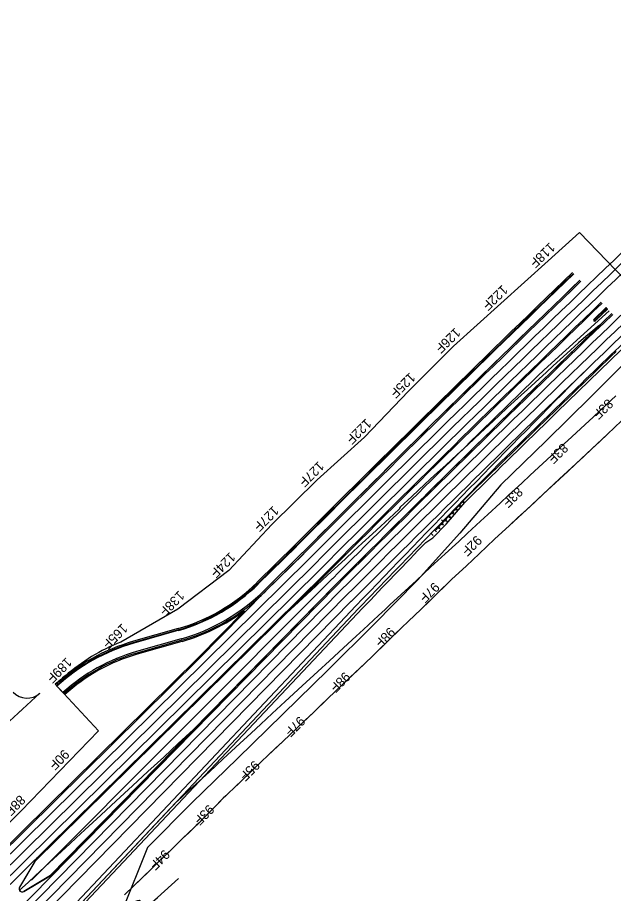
# Model space of a CAD drawing. Extents: x 2163396 to 2173129, y 605545 to 614595.
# Drawn here: x 2164110 to 2165051, y 606275 to 607658 of the extents above; entities that cross this region are included whole.
import ezdxf

# ---------------------------------------------------------------- set-up
doc = ezdxf.new("R2010")
doc.units = 0
for name, color, linetype in [('RD_PD_AsphRem', 7, 'Continuous'), ('RD_PD_CstnLmt', 7, 'Continuous'), ('RD_PD_DR_Ditch', 7, 'Continuous'), ('RD_PD_EarthShd', 7, 'Continuous'), ('RD_PD_Final_LnLine', 7, 'Continuous'), ('RD_PD_Final_TrvlWay', 7, 'Continuous'), ('RD_PD_GR', 7, 'Continuous'), ('RD_PD_MedBWall', 7, 'Continuous'), ('RD_PD_MedGR', 7, 'Continuous'), ('RD_PD_TX_CstnLmt', 7, 'Continuous')]:
    doc.layers.add(name, color=color, linetype=linetype)

msp = doc.modelspace()

# ---------------------------------------------------------------- linework, layer by layer
at = {"layer": 'RD_PD_AsphRem'}
for p, q in [((2164161.6, 606303.2), (2164392.3, 606538.4)), ((2164363.7, 606512.1), (2164387.6, 606534.1)), ((2164387.6, 606534.1), (2164392.3, 606538.4)), ((2164359.8, 606418.6), (2164041.5, 606080.9)), ((2164202.4, 606362.7), (2164216.2, 606375.5)), ((2164137.3, 606325.6), (2164113, 606285)), ((2164112.9, 606280.1), (2164126.6, 606292.6)), ((2164119.9, 606278.2), (2164161.6, 606303.2))]:
    msp.add_line(p, q, dxfattribs=at)
for points in [[(2165028.9, 607172.3), (2165025.7, 607169.6), (2165018.2, 607163.2), (2165007.3, 607154.1), (2164995.5, 607144.2), (2164977.1, 607127.7), (2164966.3, 607117.9), (2164955.5, 607107.9), (2164944.9, 607098.2), (2164927.2, 607081.9), (2164914.8, 607070.7), (2164904.8, 607061.6), (2164883.6, 607042.3), (2164870.3, 607029.7), (2164861.4, 607021.4), (2164840.2, 607001.5), (2164821.2, 606984.1), (2164803.3, 606967.5), (2164786.1, 606951.4), (2164768.4, 606935.6), (2164752.9, 606921.1), (2164732.2, 606901.8), (2164714.1, 606884.8), (2164713, 606883.4), (2164712.9, 606882.7), (2164712.9, 606882.2), (2164703.9, 606874), (2164683.3, 606855.1), (2164670.3, 606843.1), (2164654.1, 606828.2), (2164640.5, 606815.5), (2164627.4, 606803.2), (2164621.4, 606797.6), (2164599.2, 606777.4), (2164573.5, 606753.4), (2164547.1, 606729.2), (2164535.6, 606718.5)], [(2165054.3, 607060.5), (2165039.8, 607047), (2165018.4, 607027.2), (2165006.1, 607015.5), (2164984.9, 606995.8), (2164973.1, 606984.8), (2164952.5, 606966), (2164939.3, 606953.9), (2164919.3, 606935.2), (2164905.8, 606922.8), (2164885.2, 606903.8), (2164871.6, 606891.2), (2164852.1, 606873.2), (2164840.7, 606862.7), (2164820, 606843.7), (2164806.4, 606830.9), (2164785.2, 606811.5), (2164762, 606790.1), (2164739.6, 606769.4), (2164715.3, 606747), (2164697.8, 606730.7), (2164690.1, 606723.5), (2164679.7, 606713.8), (2164655.8, 606691.9), (2164644.6, 606681.5), (2164624.6, 606663), (2164602.6, 606642.6), (2164584.1, 606625.6), (2164559.3, 606602.8), (2164532.5, 606578), (2164512.1, 606559.2), (2164494.1, 606542.5), (2164478.6, 606528.2), (2164461, 606512), (2164434.7, 606487.6), (2164412.7, 606467.3), (2164401.8, 606457.1), (2164391.6, 606447.8), (2164382.5, 606439.6), (2164368.7, 606426.7), (2164359.8, 606418.6)], [(2164278.7, 606273), (2164293.4, 606287.2), (2164303.3, 606296.8), (2164318.1, 606311.1), (2164328, 606320.6), (2164343.6, 606335.5), (2164355.9, 606347.5), (2164371, 606362.2), (2164388.2, 606378.8), (2164395.9, 606386.3), (2164408.3, 606398.9), (2164419.3, 606409.8), (2164434.7, 606425.3), (2164442.9, 606433.4), (2164451.8, 606441.8), (2164465.3, 606454.8), (2164483.7, 606472.2), (2164505.8, 606493.4), (2164528.8, 606515.2), (2164551.3, 606536.4), (2164576.9, 606560.9), (2164599.5, 606582.7), (2164622.2, 606604.4), (2164646.9, 606627.5), (2164670.3, 606649.8), (2164693.5, 606672.3), (2164716.8, 606695), (2164726.8, 606704.7), (2164747.2, 606724), (2164772.9, 606749.2), (2164794.8, 606770.6), (2164818.4, 606792.5), (2164838.6, 606811.5), (2164862.8, 606834.5), (2164886.5, 606856.1), (2164913.3, 606880.8), (2164939.7, 606905.2), (2164965.6, 606929.4), (2164991.3, 606953.3), (2165016.6, 606977), (2165041.4, 607000.4), (2165063.3, 607021.2)], [(2164392.3, 606538.4), (2164392.3, 606538.4), (2164614.2, 606764.6)], [(2164535.6, 606718.5), (2164137.3, 606325.6), (2164137.3, 606325.6)], [(2164392.3, 606538.4), (2164387.6, 606534.1), (2164363.7, 606512.1), (2164340.6, 606490.5), (2164315.6, 606467.5), (2164291.2, 606444.9), (2164265.5, 606421.1), (2164241.3, 606398.7), (2164216.2, 606375.5), (2164202.4, 606362.7), (2164192.2, 606353.3), (2164173, 606335.6), (2164160.4, 606323.9), (2164137.7, 606302.8), (2164126.6, 606292.6), (2164112.9, 606280.1)], [(2164315.6, 606467.5), (2164340.6, 606490.5), (2164363.7, 606512.1)], [(2164265.5, 606421.1), (2164291.2, 606444.9), (2164315.6, 606467.5)], [(2164216.2, 606375.5), (2164241.3, 606398.7), (2164265.5, 606421.1)], [(2164126.6, 606292.6), (2164137.7, 606302.8), (2164160.4, 606323.9), (2164173, 606335.6), (2164192.2, 606353.3), (2164202.4, 606362.7)]]:
    msp.add_lwpolyline(points, dxfattribs=at)
for centre, radius, start, end in [((2185842.9, 585582.7), 29988.8, 133.95223, 135.0633), ((2164117.3, 606282.5), 5, 149.0992, 208.9048), ((2164117.3, 606282.5), 5, 208.9048, 301.0267)]:
    msp.add_arc(centre, radius, start, end, dxfattribs=at)
at = {"layer": 'RD_PD_CstnLmt'}
for p, q in [((2164947.6, 607273.6), (2164997, 607318.7)), ((2165134.6, 607175.3), (2164997, 607318.7)), ((2164947.6, 607273.6), (2164872.8, 607206.5)), ((2164872.8, 607206.5), (2164798.3, 607139.1)), ((2164798.3, 607139.1), (2164727.1, 607068.3)), ((2165085.8, 607130.2), (2165015.3, 607059.6)), ((2164727.1, 607068.3), (2164657.8, 606995.6)), ((2165015.3, 607059.6), (2164944.3, 606989.6)), ((2164657.8, 606995.6), (2164583.1, 606928.3)), ((2164944.3, 606989.6), (2164872.7, 606920.2)), ((2164583.1, 606928.3), (2164511.6, 606857.8)), ((2164872.7, 606920.2), (2164808.1, 606843.7)), ((2164511.6, 606857.8), (2164443.2, 606784.7)), ((2164808.1, 606843.7), (2164741.1, 606769.6)), ((2164443.2, 606784.7), (2164362.7, 606723.8)), ((2164741.1, 606769.6), (2164671.1, 606698.7)), ((2164362.7, 606723.8), (2164273, 606672)), ((2164671.1, 606698.7), (2164600.1, 606628.2)), ((2164600.1, 606628.2), (2164528.8, 606558.2)), ((2164237.7, 606532), (2164169.5, 606605.3)), ((2164528.8, 606558.2), (2164457.3, 606488.3)), ((2164237.7, 606532), (2164115.4, 606405.5)), ((2164457.3, 606488.3), (2164385.4, 606418.7)), ((2164385.4, 606418.7), (2164315.1, 606347.6)), ((2164115.4, 606405.5), (2164043.9, 606335.6)), ((2164315.1, 606347.6), (2164274.5, 606246.8))]:
    msp.add_line(p, q, dxfattribs=at)
msp.add_lwpolyline([(2165052.4, 607010.8), (2165041.4, 607000.4), (2165029, 606988.7), (2165016.6, 606977), (2165003.9, 606965.1), (2164991.3, 606953.3), (2164978.4, 606941.3), (2164952.7, 606917.3), (2164939.7, 606905.2), (2164926.5, 606893), (2164913.3, 606880.8), (2164899.9, 606868.4), (2164886.5, 606856.1), (2164874.7, 606845.3), (2164862.8, 606834.5), (2164850.7, 606823), (2164838.6, 606811.5), (2164828.5, 606802), (2164818.4, 606792.5), (2164806.6, 606781.5), (2164794.8, 606770.6), (2164783.9, 606759.9), (2164772.9, 606749.2), (2164760, 606736.6), (2164747.2, 606724), (2164726.8, 606704.7), (2164716.8, 606695), (2164705.2, 606683.7), (2164693.5, 606672.3), (2164681.9, 606661.1), (2164670.3, 606649.8), (2164658.6, 606638.7), (2164643.1, 606623.9), (2164634.6, 606616), (2164622.2, 606604.4), (2164610.9, 606593.5), (2164599.5, 606582.7), (2164588.2, 606571.8), (2164576.9, 606560.9), (2164564.1, 606548.6), (2164551.3, 606536.4), (2164540.1, 606525.8), (2164528.8, 606515.2), (2164517.3, 606504.3), (2164505.8, 606493.4), (2164494.7, 606482.8), (2164483.7, 606472.2), (2164474.5, 606463.5), (2164465.3, 606454.8), (2164458.5, 606448.3), (2164451.8, 606441.8), (2164442.9, 606433.4), (2164438.8, 606429.3), (2164434.7, 606425.3), (2164427, 606417.5), (2164419.3, 606409.8), (2164413.8, 606404.3), (2164408.3, 606398.9), (2164402.1, 606392.6), (2164395.9, 606386.3), (2164392, 606382.5), (2164388.2, 606378.8), (2164379.6, 606370.5), (2164371, 606362.2), (2164363.4, 606354.8), (2164355.9, 606347.5), (2164349.7, 606341.5), (2164343.6, 606335.5), (2164335.8, 606328.1), (2164328, 606320.6), (2164323, 606315.8), (2164318.1, 606311.1), (2164310.7, 606303.9), (2164303.3, 606296.8), (2164298.3, 606292), (2164293.4, 606287.2), (2164289.1, 606283.1)], dxfattribs=at)
for centre, radius, start, end in [((2164387.5, 606385), 309, 111.7394, 130.9176), ((2164377.8, 606376.1), 309.7, 128.4862, 132.2696)]:
    msp.add_arc(centre, radius, start, end, dxfattribs=at)
at = {"layer": 'RD_PD_DR_Ditch'}
msp.add_open_spline([(2163992.1, 605963.5), (2164058.1, 606039), (2164126.3, 606112.1), (2164196.5, 606183.4), (2164268.9, 606252.4), (2164363.9, 606298.9), (2163992.1, 605963.5), (2164363.9, 606298.9)], degree=3, dxfattribs=at)
at = {"layer": 'RD_PD_EarthShd'}
for p, q in [((2164786.4, 606857.9), (2164815.8, 606892.1)), ((2164786.4, 606857.9), (2164765.6, 606836.3)), ((2164754.6, 606829.3), (2164765.6, 606836.3)), ((2164548, 606825.3), (2164487.7, 606765.8)), ((2164595.5, 606777.5), (2164136.9, 606325)), ((2164611.3, 606761.7), (2164160.4, 606302.6)), ((2164044.4, 606078.2), (2164654.4, 606725.4)), ((2164468.1, 606721.2), (2164394.8, 606646.9)), ((2164363.6, 606693.4), (2164292.8, 606673.2)), ((2164369.5, 606672.9), (2164298.7, 606652.7)), ((2164394.9, 606647), (2163399.7, 605664.9))]:
    msp.add_line(p, q, dxfattribs=at)
for centre, radius, start, end in [((2185842.9, 585582.7), 30078.5, 133.90116, 135.07107), ((2185842.9, 585582.7), 30011.2, 133.90125, 135.07107), ((2185842.9, 585582.7), 29988.8, 133.90127, 135.07107), ((2185842.9, 585582.7), 29937.1, 133.90134, 134.61799), ((2186224.2, 586047.7), 29880.1, 135.93291, 136.2097), ((2164283.7, 606973.2), 291, 285.901, 314.5289), ((2164283.7, 606973.2), 312.3, 285.959, 306.1889), ((2164377.8, 606376.1), 309, 105.959, 132.2618), ((2164377.8, 606376.1), 287.7, 105.959, 132.2303)]:
    msp.add_arc(centre, radius, start, end, dxfattribs=at)
at = {"layer": 'RD_PD_Final_LnLine'}
for p, q in [((2164549.4, 606823.9), (2164489.1, 606764.4)), ((2164550.1, 606823.1), (2164489.8, 606763.7)), ((2164560, 606813.2), (2164499.7, 606753.7)), ((2164570, 606803), (2163408.2, 605656.4)), ((2164578.5, 606794.4), (2163416.7, 605647.9)), ((2164586.9, 606785.9), (2163425.2, 605639.4)), ((2164619.7, 606753.2), (2163476.1, 605588.6)), ((2164628.3, 606744.8), (2163484.6, 605580.1)), ((2164636.8, 606736.3), (2164100.3, 606189.9)), ((2164037.1, 606085), (2164644.1, 606729)), ((2164364.2, 606691.5), (2164293.4, 606671.3)), ((2164364.4, 606690.6), (2164293.7, 606670.3)), ((2164368.1, 606677), (2164297.5, 606656.9)), ((2164172, 606602.6), (2164171.3, 606603.3)), ((2164181.5, 606592.3), (2164172, 606602.6)), ((2164141, 606331.8), (2164113, 606285)), ((2164167.3, 606306.7), (2164119.9, 606278.2))]:
    msp.add_line(p, q, dxfattribs=at)
for centre, radius, start, end in [((2185842.9, 585582.7), 30047.2, 132.71947, 135.07107), ((2185842.9, 585582.7), 30035.2, 132.71947, 135.07107), ((2185842.9, 585582.7), 30023.2, 132.71947, 135.07107), ((2185842.9, 585582.7), 29976.8, 132.71947, 135.07107), ((2185842.9, 585582.7), 29964.8, 132.71947, 135.07107), ((2185842.9, 585582.7), 29952.8, 132.71947, 134.08582), ((2185842.9, 585582.7), 30076.5, 133.90116, 135.07107), ((2185842.9, 585582.7), 30075.5, 133.90116, 135.07107), ((2185842.9, 585582.7), 30061.5, 133.90118, 135.07107), ((2185842.9, 585582.7), 29952.8, 134.08582, 135.07107), ((2186224.2, 586047.7), 29890.1, 135.23105, 136.2184), ((2164283.7, 606973.2), 293, 285.901, 314.5289), ((2164283.7, 606973.2), 294, 285.901, 314.5289), ((2164283.7, 606973.2), 308, 285.901, 314.6107), ((2164377.8, 606376.1), 307, 105.959, 132.2618), ((2164377.8, 606376.1), 306, 105.959, 132.2618), ((2164377.8, 606376.1), 292, 105.959, 132.2303), ((2164117.3, 606282.5), 5, 149.0992, 301.0267)]:
    msp.add_arc(centre, radius, start, end, dxfattribs=at)
at = {"layer": 'RD_PD_Final_TrvlWay'}
for p, q in [((2164561.6, 606811.5), (2164501.6, 606752.3)), ((2164594.1, 606778.9), (2163859.3, 606053.8)), ((2164612.7, 606760.3), (2163889.4, 606023.7)), ((2164501.6, 606752.3), (2164396.3, 606645.5)), ((2164041.5, 606080.9), (2164648.3, 606724.8)), ((2164396.3, 606645.5), (2163401.1, 605663.5)), ((2164145.1, 606591.4), (2164083.4, 606534.6))]:
    msp.add_line(p, q, dxfattribs=at)
for centre, radius, start, end in [((2185842.9, 585582.7), 30059.2, 133.90118, 135.07107), ((2185842.9, 585582.7), 30013.2, 133.90124, 135.07107), ((2185842.9, 585582.7), 29986.8, 133.90127, 135.07107), ((2185842.9, 585582.7), 29942.8, 133.90133, 134.46834), ((2186224.2, 586047.7), 29884.1, 135.61465, 136.21863), ((2164124.8, 606613.5), 30, 222.7195, 312.4957)]:
    msp.add_arc(centre, radius, start, end, dxfattribs=at)
at = {"layer": 'RD_PD_GR'}
for p, q in [((2164941.1, 607101.8), (2165044.1, 607194.9)), ((2164813.1, 606894.8), (2164770.2, 606850.1)), ((2164771.2, 606850.4), (2164813.5, 606894.4)), ((2164806.7, 606887.4), (2164808, 606888.7)), ((2164808.2, 606886), (2164806.7, 606887.4)), ((2164808, 606888.7), (2164809.4, 606887.3)), ((2164809.4, 606887.3), (2164808.2, 606886)), ((2164812.3, 606893.2), (2164813.5, 606894.4)), ((2164813.7, 606891.8), (2164812.3, 606893.2)), ((2164813.5, 606894.4), (2164813.1, 606894.8)), ((2164813.5, 606894.4), (2164814.9, 606893)), ((2164814.9, 606893), (2164813.7, 606891.8)), ((2164814.3, 606892.4), (2164815.2, 606891.6)), ((2164814.6, 606890.9), (2164815.8, 606892.2)), ((2164795.7, 606875.9), (2164796.9, 606877.1)), ((2164797.1, 606874.5), (2164795.7, 606875.9)), ((2164796.9, 606877.1), (2164798.3, 606875.7)), ((2164798.3, 606875.7), (2164797.1, 606874.5)), ((2164797.7, 606875.1), (2164798.6, 606874.2)), ((2164798, 606873.6), (2164799.2, 606874.9)), ((2164801.2, 606881.6), (2164802.4, 606882.9)), ((2164802.6, 606880.2), (2164801.2, 606881.6)), ((2164802.4, 606882.9), (2164803.9, 606881.5)), ((2164803.9, 606881.5), (2164802.6, 606880.2)), ((2164803.2, 606880.9), (2164804.2, 606880)), ((2164803.5, 606879.4), (2164804.8, 606880.6)), ((2164808.8, 606886.6), (2164809.7, 606885.8)), ((2164809.1, 606885.1), (2164810.3, 606886.4)), ((2164779, 606858.5), (2164780.3, 606859.8)), ((2164779.3, 606864.9), (2164782, 606862.3)), ((2164780.3, 606859.8), (2164781.7, 606858.4)), ((2164784.6, 606864.3), (2164785.8, 606865.6)), ((2164786, 606862.9), (2164784.6, 606864.3)), ((2164785.8, 606865.6), (2164787.2, 606864.2)), ((2164787.2, 606864.2), (2164786, 606862.9)), ((2164786.6, 606863.6), (2164787.5, 606862.7)), ((2164786.9, 606862.1), (2164788.1, 606863.3)), ((2164790.1, 606870.1), (2164791.3, 606871.4)), ((2164791.6, 606868.7), (2164790.1, 606870.1)), ((2164791.3, 606871.4), (2164792.8, 606870)), ((2164792.8, 606870), (2164791.6, 606868.7)), ((2164792.2, 606869.3), (2164793.1, 606868.5)), ((2164792.5, 606867.8), (2164793.7, 606869.1)), ((2164768.8, 606848.6), (2164771.5, 606846)), ((2164770.2, 606850.1), (2164770.9, 606849.4)), ((2164770.9, 606849.4), (2164771.6, 606850.1)), ((2164771.6, 606850.1), (2164771.2, 606850.4)), ((2164773.5, 606852.8), (2164774.7, 606854)), ((2164774.9, 606851.4), (2164773.5, 606852.8)), ((2164774.7, 606854), (2164776.2, 606852.7)), ((2164776.2, 606852.7), (2164774.9, 606851.4)), ((2164775.5, 606852), (2164776.4, 606851.2)), ((2164775.8, 606850.5), (2164777.1, 606851.8)), ((2164780.5, 606857.2), (2164779, 606858.5)), ((2164781.7, 606858.4), (2164780.5, 606857.2)), ((2164781.1, 606857.8), (2164782, 606856.9)), ((2164781.4, 606856.3), (2164782.6, 606857.6)), ((2164763.3, 606842.8), (2164766, 606840.2)), ((2164606.9, 606772.1), (2164132, 606296.1))]:
    msp.add_line(p, q, dxfattribs=at)
for radius, start, end in [(29940.8, 133.97214, 134.61799), (29999.2, 134.16623, 135.06291)]:
    msp.add_arc((2185842.9, 585582.7), radius, start, end, dxfattribs=at)
at = {"layer": 'RD_PD_MedBWall'}
for p, q in [((2164561.6, 606811.5), (2164501.6, 606752.3)), ((2164561.5, 606811.4), (2164501.6, 606752.3)), ((2164369, 606674.9), (2164298.2, 606654.6)), ((2164368.3, 606677.1), (2164301.3, 606657.9)), ((2164183.1, 606590.6), (2164181.5, 606592.3))]:
    msp.add_line(p, q, dxfattribs=at)
for centre, radius, start, end in [((2185842.9, 585582.7), 30059.2, 133.90118, 135.07107), ((2185842.9, 585582.7), 30061.5, 133.90118, 135.06255), ((2164283.7, 606973.2), 310.3, 285.959, 314.6107), ((2164377.8, 606376.1), 289.7, 105.959, 132.2303)]:
    msp.add_arc(centre, radius, start, end, dxfattribs=at)
at = {"layer": 'RD_PD_MedGR'}
for p, q in [((2165039.2, 607200), (2165019.7, 607181.3)), ((2165039.2, 607200), (2165019.7, 607181.3)), ((2165036.7, 607196.9), (2165020.1, 607180.9)), ((2165038.3, 607195.2), (2165021.7, 607179.2)), ((2165041.5, 607197.6), (2165022, 607178.9)), ((2165022, 607178.9), (2165041.5, 607197.6)), ((2165028.7, 607189.2), (2165030.6, 607191.1)), ((2165030.6, 607191.1), (2165030.9, 607191.3)), ((2165032.2, 607189.4), (2165030.6, 607191.1)), ((2165030.9, 607191.3), (2165032.8, 607193.1)), ((2165032.5, 607189.6), (2165030.9, 607191.3)), ((2165032.8, 607193.1), (2165033, 607193.4)), ((2165034.4, 607191.4), (2165032.8, 607193.1)), ((2165033, 607193.4), (2165034.9, 607195.2)), ((2165034.7, 607191.7), (2165033, 607193.4)), ((2165034.9, 607195.2), (2165035.2, 607195.5)), ((2165036.5, 607193.5), (2165034.9, 607195.2)), ((2165035.2, 607195.5), (2165036.7, 607196.9)), ((2165036.8, 607193.8), (2165035.2, 607195.5)), ((2165039.5, 607199.6), (2165036.7, 607196.9)), ((2165036.7, 607196.9), (2165039.5, 607199.6)), ((2165038.3, 607195.2), (2165036.7, 607196.9)), ((2165041.2, 607198), (2165038.3, 607195.2)), ((2165041.2, 607198), (2165038.3, 607195.2)), ((2165039.2, 607200), (2165039.5, 607199.6)), ((2165039.5, 607199.6), (2165039.2, 607200)), ((2165041.5, 607197.6), (2165041.2, 607198)), ((2165041.5, 607197.6), (2165041.2, 607198)), ((2165022, 607178.9), (2165019.7, 607181.3)), ((2165020, 607181), (2165019.7, 607181.3)), ((2165022, 607178.9), (2165021.8, 607179.2)), ((2165023.6, 607181.1), (2165021.9, 607182.7)), ((2165022.2, 607183), (2165024.1, 607184.8)), ((2165023.9, 607181.3), (2165022.2, 607183)), ((2165024.1, 607184.8), (2165024.4, 607185.1)), ((2165025.7, 607183.1), (2165024.1, 607184.8)), ((2165024.4, 607185.1), (2165026.3, 607186.9)), ((2165026, 607183.4), (2165024.4, 607185.1)), ((2165026.3, 607186.9), (2165026.6, 607187.2)), ((2165027.9, 607185.2), (2165026.3, 607186.9)), ((2165026.6, 607187.2), (2165028.4, 607189)), ((2165028.2, 607185.5), (2165026.6, 607187.2)), ((2165028.4, 607189), (2165028.7, 607189.2)), ((2165030.1, 607187.3), (2165028.4, 607189)), ((2165030.3, 607187.6), (2165028.7, 607189.2))]:
    msp.add_line(p, q, dxfattribs=at)
for points in [[(2165038.3, 607195.2), (2165036.8, 607193.8), (2165036.5, 607193.5), (2165034.7, 607191.7), (2165034.4, 607191.4), (2165032.5, 607189.6), (2165032.2, 607189.4), (2165030.3, 607187.6), (2165030.1, 607187.3), (2165028.2, 607185.5), (2165027.9, 607185.2), (2165026, 607183.4), (2165025.7, 607183.1), (2165023.9, 607181.3), (2165023.6, 607181.1), (2165021.7, 607179.2)], [(2165019.7, 607181.3), (2165020, 607181), (2165020.1, 607180.9)], [(2165020.1, 607180.9), (2165021.9, 607182.7), (2165022.2, 607183)], [(2165021.7, 607179.2), (2165021.8, 607179.2), (2165022, 607178.9)]]:
    msp.add_lwpolyline(points, dxfattribs=at)
for radius in [1.67, 1.67, 1.27, 1.27]:
    msp.add_arc((2165020.9, 607180.1), radius, 133.8803, 313.8803, dxfattribs=at)

# ---------------------------------------------------------------- texts
at = {"layer": 'RD_PD_TX_CstnLmt'}
for s, rotation, p in [('118F', 223.9297, (2164950, 607303.8)), ('122F', 224.1207, (2164875.2, 607236.7)), ('126F', 224.3117, (2164800.6, 607169.2)), ('125F', 224.5026, (2164729.2, 607098.5)), ('83F', 224.1207, (2165041.5, 607057)), ('122F', 224.6936, (2164659.9, 607025.7)), ('83F', 224.3117, (2164970.4, 606987.1)), ('127F', 224.8846, (2164585.1, 606958.4)), ('83F', 224.5026, (2164898.8, 606917.8)), ('127F', 225.0711, (2164513.5, 606887.9)), ('92F', 224.6936, (2164834.2, 606841.4)), ('124F', 225.0711, (2164445.1, 606814.9)), ('97F', 224.8846, (2164767.3, 606767.5)), ('138F', 225.0711, (2164364.6, 606754)), ('165F', 225.0711, (2164274.9, 606702.2)), ('98F', 225.0711, (2164697.2, 606696.6)), ('189F', 225.0711, (2164186.9, 606648.7)), ('98F', 225.0711, (2164626.3, 606626.1)), ('97F', 225.0711, (2164555, 606556.1)), ('90F', 225.0711, (2164182.8, 606503.6)), ('95F', 225.0711, (2164483.4, 606486.2)), ('88F', 225.0711, (2164113.3, 606431.6)), ('93F', 225.0711, (2164411.5, 606416.6)), ('94F', 225.0711, (2164341.3, 606345.5))]:
    msp.add_text(s, height=15, rotation=rotation, dxfattribs=at).set_placement(p)

doc.saveas('drawing.dxf')
